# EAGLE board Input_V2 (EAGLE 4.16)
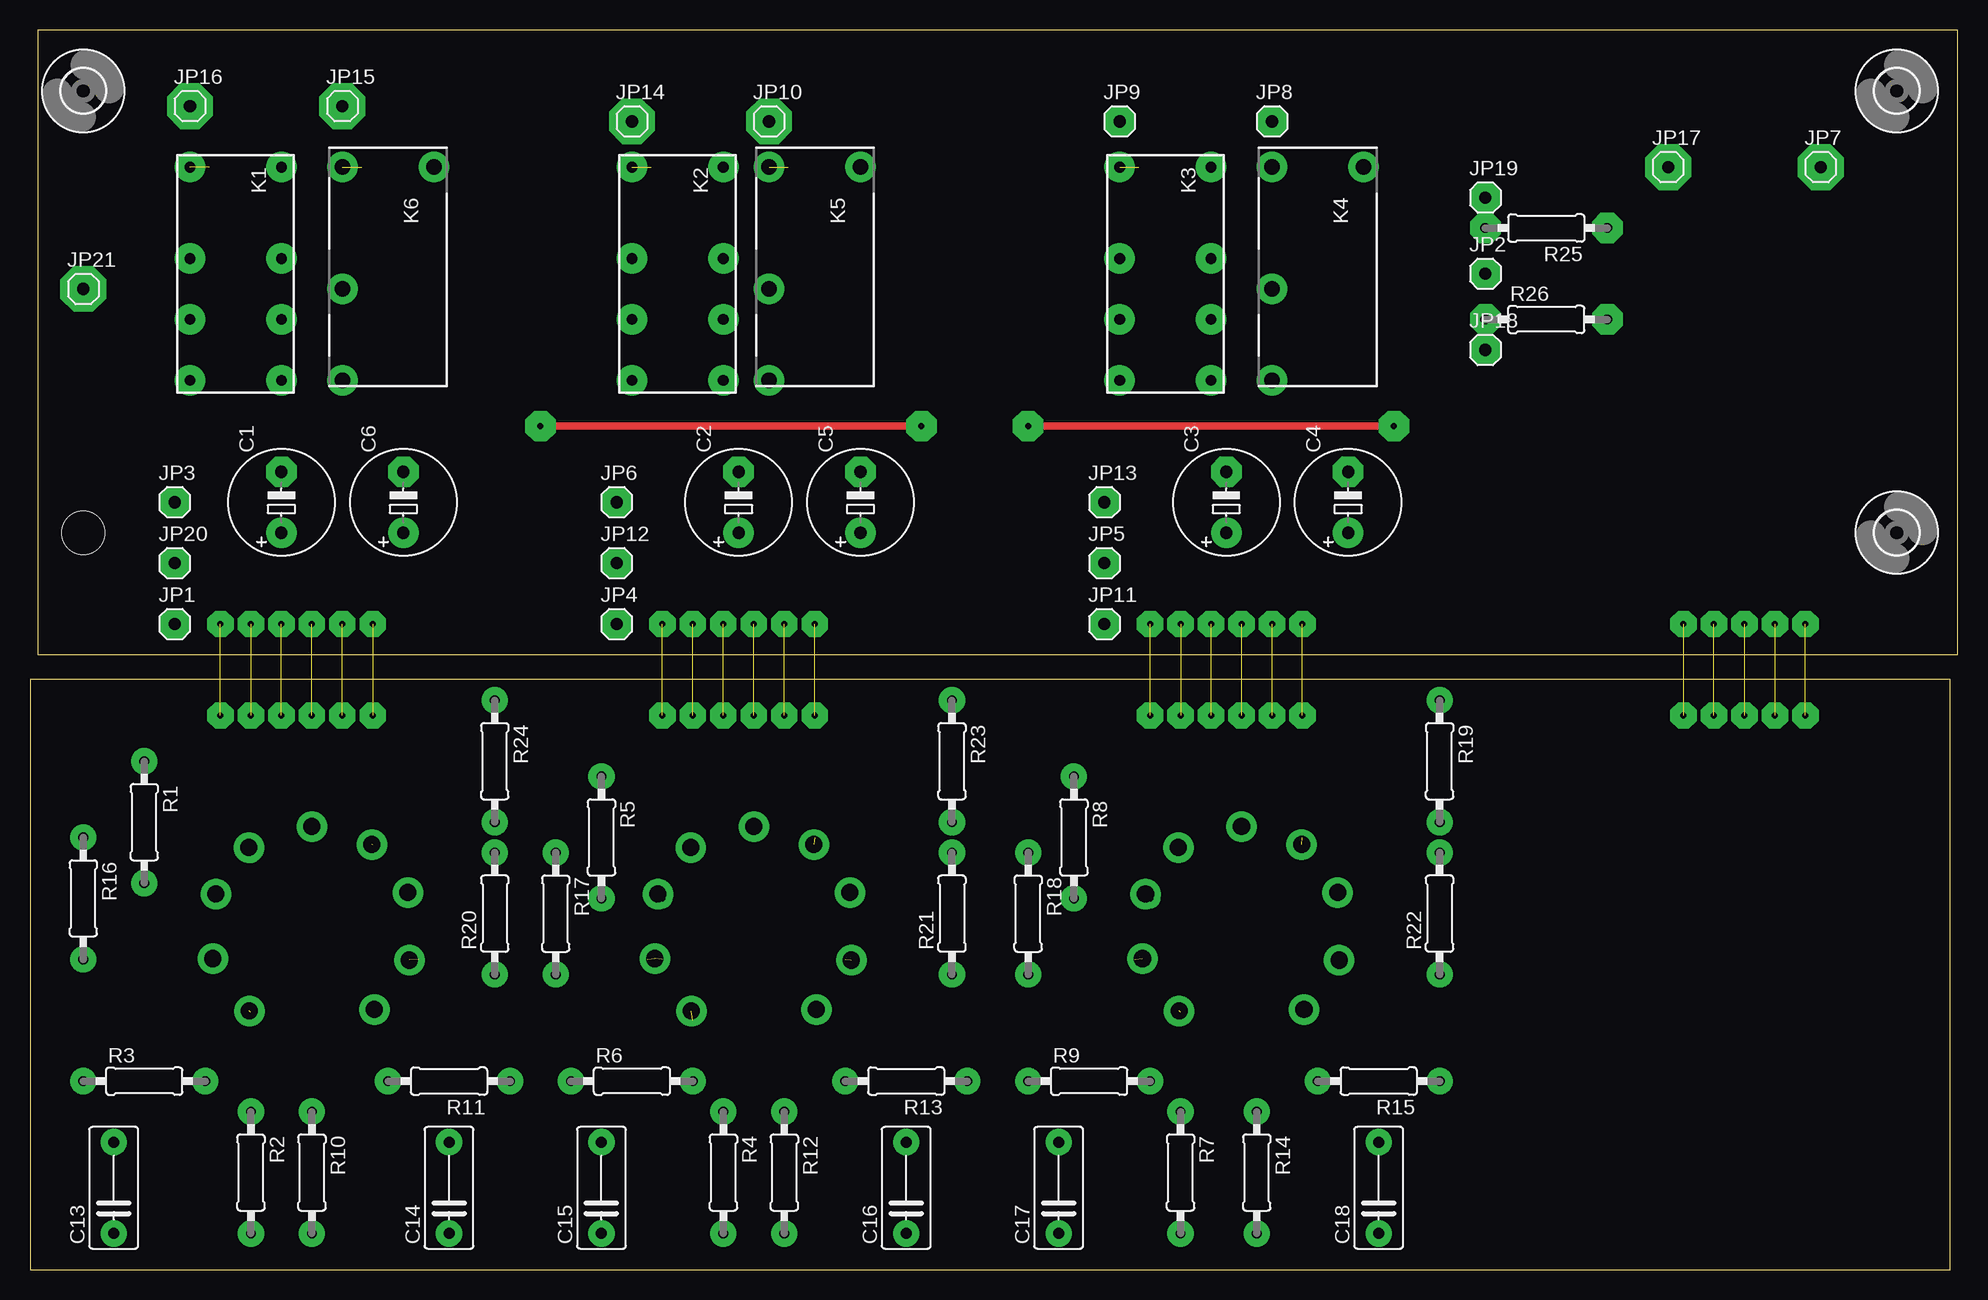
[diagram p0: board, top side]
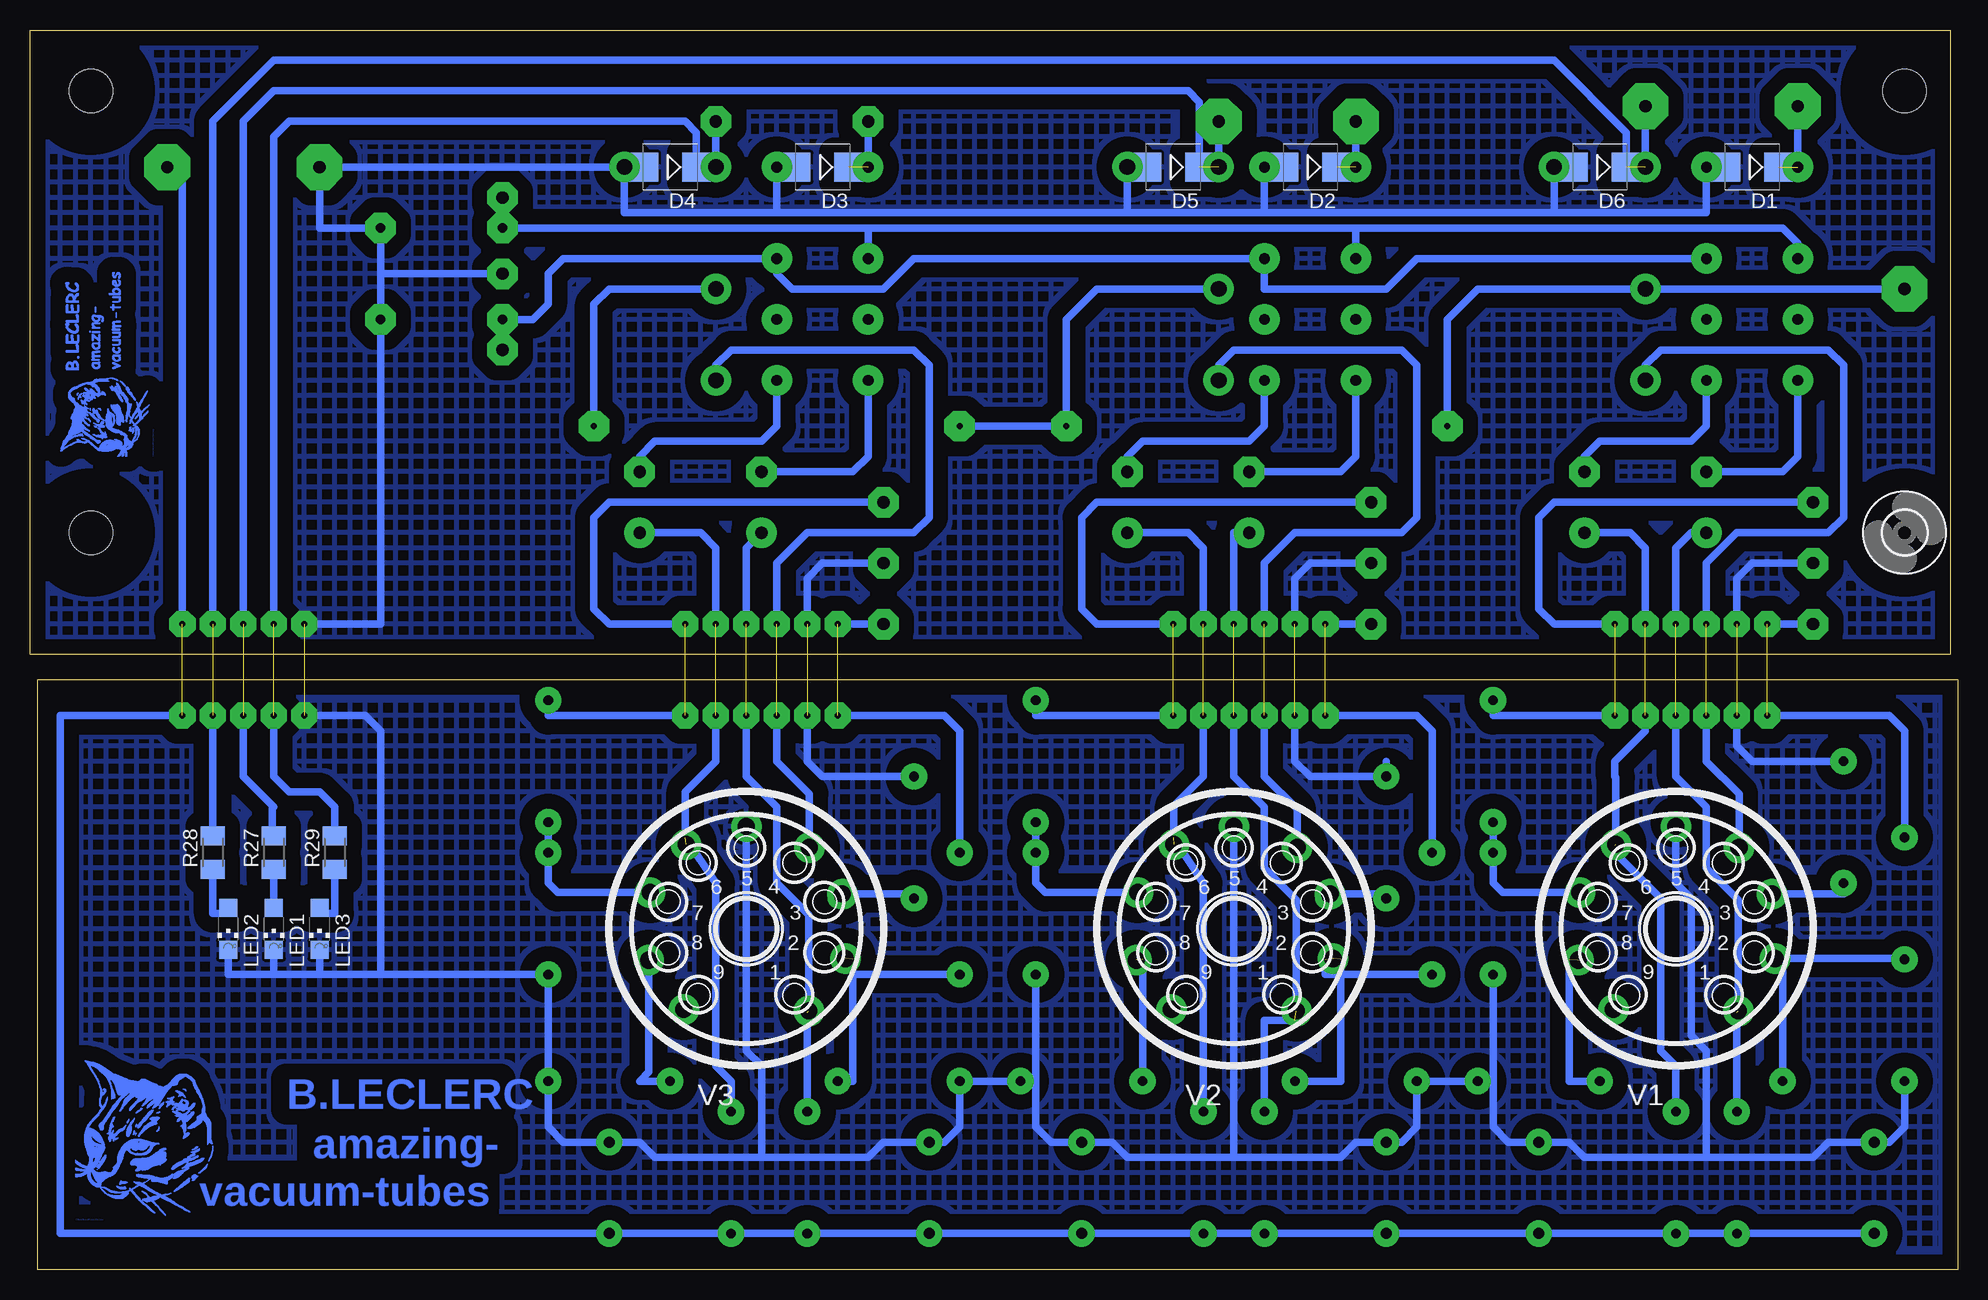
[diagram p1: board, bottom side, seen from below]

Size 160.65 x 103.34 mm. Coordinates in mm from the lower left corner, seen from the top.
Outline: 0,0 160,0 160,49.2 0,49.2 0,0
Outline: 0.63,51.27 160.65,51.27 160.65,103.34 0.63,103.34 0.63,51.27
Copper layers (1*16): Top 0.035mm / dielectric 1.5mm / Bottom 0.035mm
Design rules "default": minimum track width 10mil, minimum drill 24mil, track to track 8mil, track to pad 8mil, pad to pad 8mil, via to via 8mil, smd to smd 8mil, copper to edge 40mil, drill to drill 8mil, minimum pad ring 10mil, minimum via ring 8mil, stop-mask expansion 4mil, vias tented up to drill 0mil, thermal gap 10mil

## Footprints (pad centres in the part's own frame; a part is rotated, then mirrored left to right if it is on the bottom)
E5-8,5 = drill 1.016 pad 2.54 round: + -2.54,0 | drill 1.016 pad 2.54 octagon: - 2.54,0
C075-042X103 = drill 0.914 octagon: 1 -3.81,0; 2 3.81,0
SMB = smd 2.4 x 2.4: A 2.2,0; C -2.2,0
3,6 = hole 3.6: 0,0
1X01 = drill 1.016 octagon: 1 0,0
DS2Y = drill 0.9 round: 1 -8.89,-3.81; 4 -1.27,-3.81; 6 3.81,-3.81; 8 8.89,-3.81; 9 8.89,3.81; 11 3.81,3.81; 13 -1.27,3.81; 16 -8.89,3.81
RE-SCHRACK = drill 1.3 round: 11 8.89,-3.81; 14 1.27,-3.81; A1 -8.89,-3.81; A2 -8.89,3.81
CHIPLED_1206 = smd 1.5 x 1.5: A 0,-1.75; C 0,1.75
0207/10 = drill 0.813 octagon: 1 -5.08,0; 2 5.08,0
M1206 = smd 1.6 x 2: 1 -1.4,0; 2 1.4,0
NOVAL = drill 1.422 pad 2.54 round: 1 5.207,-6.858; 2 8.254,-2.484; 3 8.004,2.893; 4 5.258,6.77; 5 0,8.524; 6 -5.004,7.024; 7 -8.004,3.02; 8 -8.127,-2.611; 9 -5.207,-6.731

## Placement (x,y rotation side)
C1  4,7µF/100V  [E5-8,5]  20.95,63.97 90 top
C2  4,7µF/100V  [E5-8,5]  59.05,63.97 90 top
C3  4,7µF/100V  [E5-8,5]  99.69,63.97 90 top
C4  4,7µF/100V  [E5-8,5]  109.85,63.97 90 top
C5  4,7µF/100V  [E5-8,5]  69.21,63.97 90 top
C6  4,7µF/100V  [E5-8,5]  31.11,63.97 90 top
C13  0.47  [C075-042X103]  6.98,6.82 90 top
C14  0.47  [C075-042X103]  34.92,6.82 90 top
C15  0.47  [C075-042X103]  47.62,6.82 90 top
C16  0.47  [C075-042X103]  73.02,6.82 90 top
C17  0.47  [C075-042X103]  85.72,6.82 90 top
C18  0.47  [C075-042X103]  112.39,6.82 90 top
D1  1N4148  [SMB]  17.14,91.91 180 bottom
D2  1N4148  [SMB]  53.97,91.91 180 bottom
D3  1N4148  [SMB]  94.61,91.91 180 bottom
D4  1N4148  [SMB]  107.31,91.91 180 bottom
D5  1N4148  [SMB]  65.4,91.91 180 bottom
D6  1N4148  [SMB]  29.84,91.91 180 bottom
H1  MOUNT-HOLE3.6  [3,6]  4.44,61.43 0 bottom
H2  MOUNT-HOLE3.6  [3,6]  155.57,61.43 0 top
H3  MOUNT-HOLE3.6  [3,6]  155.57,98.26 0 top
H4  MOUNT-HOLE3.6  [3,6]  4.44,98.26 0 top
JP1  IN1_L  [1X01]  12.06,53.81 0 top
JP2  IN_GND_1  [1X01]  121.28,83.02 0 top
JP3  IN1_R  [1X01]  12.06,63.97 0 top
JP4  IN2_L  [1X01]  48.89,53.81 0 top
JP5  IN_GND_2  [1X01]  89.53,58.89 0 top
JP6  IN2_R  [1X01]  48.89,63.97 0 top
JP7  VCC  [1X01]  149.22,91.91 0 top
JP8  [1X01]  103.5,95.72 0 top
JP9  [1X01]  90.8,95.72 0 top
JP10  [1X01]  61.59,95.72 0 top
JP11  IN3_L  [1X01]  89.53,53.81 0 top
JP12  IN_GND_3  [1X01]  48.89,58.89 0 top
JP13  IN3_R  [1X01]  89.53,63.97 0 top
JP14  [1X01]  50.16,95.72 0 top
JP15  [1X01]  26.03,96.99 0 top
JP16  [1X01]  13.33,96.99 0 top
JP17  [1X01]  136.52,91.91 0 top
JP18  OUT_L  [1X01]  121.28,76.67 0 top
JP19  OUT_R  [1X01]  121.28,89.37 0 top
JP20  GND  [1X01]  12.06,58.89 0 top
JP21  [1X01]  4.44,81.75 0 top
K1  DS2Y-S-DC12V  [DS2Y]  17.14,83.02 270 top
K2  DS2Y-S-DC12V  [DS2Y]  53.97,83.02 270 top
K3  DS2Y-S-DC12V  [DS2Y]  94.61,83.02 270 top
K4  RE030005  [RE-SCHRACK]  107.31,83.02 270 top
K5  RE030005  [RE-SCHRACK]  65.4,83.02 270 top
K6  RE030005  [RE-SCHRACK]  29.84,83.02 270 top
LED1  Red  [CHIPLED_1206]  140.33,28.41 180 bottom
LED2  Green  [CHIPLED_1206]  144.14,28.41 180 bottom
LED3  Blue  [CHIPLED_1206]  136.52,28.41 180 bottom
R1  1K  [0207/10]  9.52,37.3 270 top
R2  10K  [0207/10]  18.41,8.09 270 top
R3  47K  [0207/10]  9.52,15.71 0 top
R4  10K  [0207/10]  57.78,8.09 270 top
R5  1K  [0207/10]  47.62,36.03 270 top
R6  47K  [0207/10]  50.16,15.71 0 top
R7  10K  [0207/10]  95.88,8.09 270 top
R8  1K  [0207/10]  86.99,36.03 270 top
R9  47K  [0207/10]  88.26,15.71 0 top
R10  10K  [0207/10]  23.49,8.09 270 top
R11  1K  [0207/10]  34.92,15.71 180 top
R12  10K  [0207/10]  62.86,8.09 270 top
R13  1K  [0207/10]  73.02,15.71 180 top
R14  10K  [0207/10]  102.23,8.09 270 top
R15  1K  [0207/10]  112.39,15.71 180 top
R16  22K  [0207/10]  4.44,30.95 270 top
R17  22K  [0207/10]  43.81,29.68 270 top
R18  22K  [0207/10]  83.18,29.68 270 top
R19  22K  [0207/10]  117.47,42.38 270 top
R20  47K  [0207/10]  38.73,29.68 90 top
R21  47K  [0207/10]  76.83,29.68 90 top
R22  47K  [0207/10]  117.47,29.68 90 top
R23  22K  [0207/10]  76.83,42.38 270 top
R24  22K  [0207/10]  38.73,42.38 270 top
R25  220K  [0207/10]  126.36,86.83 180 top
R26  220K  [0207/10]  126.36,79.21 0 top
R27  1200  [M1206]  140.33,34.76 90 bottom
R28  1200  [M1206]  145.41,34.76 90 bottom
R29  1200  [M1206]  135.25,34.76 90 bottom
U$3  [CHAT1]  156.84,4.28 0 bottom
U$4  [CHAT]  150.49,67.78 90 bottom
V1  ECC82  [NOVAL]  23.49,28.41 0 bottom
V2  ECC82  [NOVAL]  60.32,28.41 0 bottom
V3  ECC82  [NOVAL]  100.96,28.41 0 bottom

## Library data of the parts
C1-C6 C13-C18 R1-R29 = rcl
D1-D6 = diode
H1-H4 = holes
JP1-JP21 = pinhead
K1-K6 = relay
LED1-LED3 = led
U$3 U$4 = LOGO
V1-V3 = tubes

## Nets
CD-E1: D1.C JP16.1 K1.1
CD-E2: D2.C JP14.1 K2.1
CD-E3: D3.C JP9.1 K3.1
GND: C13.2 C14.2 C15.2 C16.2 C17.2 C18.2 D1.A D2.A D3.A D4.A D5.A D6.A JP2.1 JP5.1 JP12.1 JP17.1 JP20.1 K1.16 K2.16 K3.16 K4.A2 K5.A2 K6.A2 LED1.C LED2.C LED3.C R1.1 R3.1 R5.1 R6.1 R8.1 R9.1 R11.1 R13.1 R15.1 R20.1 R21.1 R22.1 R25.1 R26.2 V1.5 V3.5
N$1: C2.+ R4.1 V2.1
N$2: C3.+ R7.1 V3.1
N$3: R8.2 V3.3
N$4: C6.+ R10.1 V1.6
N$5: R11.2 V1.8
N$7: R13.2 V2.8
N$8: C4.+ R14.1 V3.6
N$9: R15.2 V3.8
N$10: R1.2 V1.3
N$11: R3.2 R16.2 V1.2
N$12: C1.+ R2.1 V1.1
N$13: JP1.1 R16.1
N$14: JP4.1 R17.1
N$15: R5.2 V2.3
N$16: JP11.1 R18.1
N$17: JP3.1 R24.1
N$18: R6.2 R17.2 V2.2
N$19: JP6.1 R23.1
N$20: R20.2 R24.2 V1.7
N$21: R9.2 R18.2 V3.2
N$22: JP13.1 R19.1
N$23: LED3.A R29.1
N$24: LED2.A R28.1
N$25: R21.2 R23.2 V2.7
N$26: LED1.A R27.1
N$27: R19.2 R22.2 V3.7
N$28: D5.C JP10.1 K5.A1 R27.2
N$30: D6.C JP15.1 K6.A1 R28.2
N$36: JP19.1 K1.4 K2.4 K3.4 R25.2
N$37: JP18.1 K1.13 K2.13 K3.13 R26.1
N$47: K4.11 V3.4
N$48: K5.11 V2.4
N$49: K6.11 V1.4
N$73: C5.+ R12.1 V2.6
N$166: D4.C JP8.1 K4.A1 R29.2
S1-L: C6.- K1.9
S1-R: C1.- K1.8
S2-L: C5.- K2.9
S2-R: C2.- K2.8
S3-L: C4.- K3.9
S3-R: C3.- K3.8
VCC: C13.1 C14.1 C15.1 C16.1 C17.1 C18.1 JP7.1 R2.2 R4.2 R7.2 R10.2 R12.2 R14.2
VCC/2: JP21.1 K4.14 K5.14 K6.14

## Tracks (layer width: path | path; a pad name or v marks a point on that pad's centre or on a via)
CD-E1  (1 unrouted)
  Bottom 0.61: K1.1 JP16.1
CD-E2  (1 unrouted)
  Bottom 0.61: K2.1 JP14.1
CD-E3  (1 unrouted)
  Bottom 0.61: K3.1 JP9.1
GND  (via drill 0.5 pad 1.68, 0.5 pad 2.18)  (4 unrouted)
  Bottom 0.61: R1.1 17.14,42.38 18.41,43.65 18.41,46.19 | JP20.1 17.14,58.89 18.41,57.62 18.41,53.81 | R3.1 4.44,11.9 5.71,10.63 C13.2 10.79,10.63 12.06,9.36 20.95,9.36 | 20.95,9.36 31.11,9.36 32.38,10.63 C14.2 37.46,10.63 38.73,11.9 38.73,15.71 | 60.32,9.36 51.43,9.36 50.16,10.63 C15.2 46.35,10.63 45.08,11.9 R6.1 R11.1 38.73,15.71 | 60.32,9.36 69.21,9.36 70.48,10.63 C16.2 75.56,10.63 76.83,11.9 76.83,15.71 | 99.69,9.36 90.8,9.36 89.53,10.63 C17.2 84.45,10.63 83.18,11.9 R9.1 R13.1 76.83,15.71 | 99.69,9.36 108.58,9.36 109.85,10.63 C18.2 116.2,10.63 117.47,11.9 R15.1 R22.1 131.44,24.6 | LED2.C 144.14,24.6 140.33,24.6 | 131.44,24.6 136.52,24.6 | 136.52,24.6 140.33,24.6 | 140.33,24.6 LED1.C | 136.52,24.6 LED3.C | 76.83,15.71 R21.1 | 38.73,15.71 R20.1 | 20.95,9.36 20.95,18.25 22.22,19.52 22.22,30.95 23.49,32.22 V1.5 23.49,37.3 | 60.32,9.36 v60.32,36.66 | v100.96,36.66 100.96,18.25 99.69,16.98 99.69,9.36 | 47.62,42.38 R5.1 53.97,41.11 55.24,42.38 55.24,46.19 | R8.1 94.61,41.11 95.88,42.38 95.88,46.19 | JP5.1 94.61,58.89 95.88,57.62 95.88,53.81 | JP12.1 53.97,58.89 55.24,57.62 55.24,53.81 | 131.44,24.6 131.44,44.92 132.71,46.19 v137.79,46.19 | 131.44,83.02 R25.1 136.52,86.83 JP17.1 K4.A2 111.12,88.1 98.42,88.1 | 131.44,83.02 JP2.1 | v137.79,53.81 131.44,53.81 R26.2 131.44,83.02 | K1.16 20.95,88.1 33.65,88.1 | 33.65,88.1 57.78,88.1 | 57.78,88.1 69.21,88.1 | 69.21,88.1 98.42,88.1 | 33.65,88.1 K6.A2 | 57.78,88.1 K2.16 | 69.21,88.1 K5.A2 | 98.42,88.1 K3.16
  pour Bottom (isolate 1.27, hatched): 0.63,48.73 159.38,48.73 159.38,0.47 0.63,0.47
  pour Bottom (isolate 1.27, hatched): 0.63,103.34 160.65,103.34 160.65,51.27 0.63,51.27 0.63,103.34 0.63,102.07
N$1  (2 unrouted)
  Bottom 0.61: R4.1 57.78,20.79 55.24,20.79 | V2.1 55.11,30.82 57.78,33.49 57.78,38.57 60.32,41.11 60.32,46.19 | C2.+ 60.32,61.43 60.32,53.81
N$2  (via drill 0.5 pad 1.68)  (2 unrouted)
  Bottom 0.61: R7.1 v95.88,21.42 95.88,22.06 | V3.1 95.75,29.55 98.42,32.22 98.42,38.57 100.96,41.11 100.96,46.19 | C3.+ 100.96,60.16 100.96,53.81
N$3
  Bottom 0.61: V3.3 87.34,31.3 R8.2
N$4  (via drill 0.5 pad 1.68)  (2 unrouted)
  Bottom 0.61: 28.57,36.03 v28.57,35.39 28.57,34.76 24.76,30.95 24.76,18.25 23.49,16.98 R10.1 | C6.+ 27.3,61.43 26.03,60.16 26.03,53.81 | V1.6 28.49,41.03 28.57,41.11 28.57,42.38 26.03,44.92 26.03,46.19
N$5  (1 unrouted)
  Bottom 0.61: R11.2 32.38,15.71 32.38,25.87
N$6  (via drill 0.5 pad 2.18)
  other vias: 140.33,46.19
N$7  (1 unrouted)
  Bottom 0.61: R13.2 67.94,25.87
N$8  (2 unrouted)
  Bottom 0.61: R14.1 102.23,15.71 103.5,16.98 103.5,32.22 106.04,36.03 106.04,39.84 103.5,42.38 103.5,46.19 | C4.+ 104.77,61.43 103.5,60.16 103.5,53.81
N$9
  Bottom 0.61: V3.8 109.09,16.47 109.85,15.71 R15.2
N$10
  Bottom 0.61: V1.3 9.52,31.3 R1.2
N$11
  Bottom 0.61: 14.6,25.93 4.44,25.93 R16.2 | 14.6,25.93 V1.2 | 14.6,25.93 R3.2
N$12  (via drill 0.5 pad 1.68)  (2 unrouted)
  Bottom 0.61: R2.1 v18.41,21.42 18.41,22.06 | C1.+ 22.22,61.43 23.49,60.16 23.49,53.81 | V1.1 18.28,30.82 20.95,33.49 20.95,38.57 23.49,41.11 23.49,46.19
N$13  (1 unrouted)
  Bottom 0.61: R16.1 4.44,44.92 5.71,46.19 15.87,46.19 | JP1.1 15.87,53.81
N$14  (1 unrouted)
  Bottom 0.61: R17.1 43.81,44.92 45.08,46.19 52.7,46.19 | JP4.1 52.7,53.81
N$15
  Bottom 0.61: V2.3 47.97,31.3 R5.2
N$16  (1 unrouted)
  Bottom 0.61: R18.1 83.18,44.92 84.45,46.19 93.34,46.19 | JP11.1 93.34,53.81
N$17  (1 unrouted)
  Bottom 0.61: R24.1 38.73,46.19 28.57,46.19 | JP3.1 33.65,63.97 34.92,62.7 34.92,55.08 33.65,53.81 28.57,53.81
N$18  (2 unrouted)
  Bottom 0.61: R17.2 52.7,24.6 52.7,25.87 | R6.2 51.43,15.71 51.43,25.87
N$19  (1 unrouted)
  Bottom 0.61: R23.1 76.83,46.19 65.4,46.19 | JP6.1 71.75,63.97 73.02,62.7 73.02,55.08 71.75,53.81 65.4,53.81
N$20
  Bottom 0.61: V1.7 37.94,31.43 38.73,32.22 R20.2 R24.2
N$21  (1 unrouted)
  Bottom 0.61: R18.2 92.07,24.6 92.07,25.87 92.07,15.71 R9.2
N$22  (1 unrouted)
  Bottom 0.61: R19.1 117.47,46.19 106.04,46.19 | JP13.1 112.39,63.97 113.66,62.7 113.66,55.08 112.39,53.81 106.04,53.81
N$23
  Bottom 0.61: R29.1 135.25,29.68 136.52,29.68 LED3.A
N$24
  Bottom 0.61: R28.1 145.41,29.68 144.14,29.68 LED2.A
N$25
  Bottom 0.61: V2.7 76.04,31.43 76.83,32.22 R21.2 R23.2
N$26
  Bottom 0.61: 140.33,29.68 LED1.A R27.1
N$27
  Bottom 0.61: V3.7 116.68,31.43 117.47,32.22 R22.2 R19.2
N$28  (2 unrouted)
  Bottom 0.61: R27.2 140.46,36.16 140.46,38.44 140.33,38.57 142.87,41.11 142.87,46.19 | K5.A1 JP10.1 | 142.87,53.81 142.87,95.72 140.33,98.26 64.13,98.26 63.2,97.33 D5.C
N$29  (via drill 0.5 pad 3.81)
  other vias: 4.44,81.75
N$30  (2 unrouted)
  Bottom 0.61: R28.2 145.41,46.19 | 27.64,93.52 D6.C 27.64,94.79 33.65,100.8 140.33,100.8 145.41,95.72 145.41,53.81 | K6.A1 JP15.1
N$31  (via drill 0.5 pad 2.18)
  other vias: 140.33,53.81
N$32  (via drill 0.5 pad 2.18)
  other vias: 142.87,46.19
N$33  (via drill 0.5 pad 2.18)
  other vias: 142.87,53.81
N$34  (via drill 0.5 pad 2.54)
  other vias: 42.54,70.32
N$35  (via drill 0.5 pad 2.54)
  other vias: 74.29,70.32
N$36
  Bottom 0.61: K1.4 13.33,85.56 14.6,86.83 50.16,86.83 | 50.16,86.83 90.8,86.83 | 90.8,86.83 R25.2 JP19.1 | 50.16,86.83 K2.4 | 90.8,86.83 K3.4
N$37
  Bottom 0.61: K1.13 45.08,84.29 47.62,81.75 57.78,81.75 K2.13 86.99,84.29 89.53,81.75 97.15,81.75 98.42,83.02 K3.13 116.2,84.29 117.47,83.02 117.47,80.48 118.74,79.21 R26.1 JP18.1
N$38  (via drill 0.5 pad 2.18)
  other vias: 100.96,46.19
N$39  (via drill 0.5 pad 2.18)
  other vias: 103.5,46.19
N$40  (via drill 0.5 pad 2.18)
  other vias: 98.42,46.19
N$41  (via drill 0.5 pad 2.18)
  other vias: 98.42,53.81
N$42  (via drill 0.5 pad 2.18)
  other vias: 100.96,53.81
N$43  (via drill 0.5 pad 2.18)
  other vias: 103.5,53.81
N$44  (via drill 0.5 pad 2.18)
  other vias: 60.32,46.19
N$45  (via drill 0.5 pad 2.18)
  other vias: 62.86,46.19
N$46  (via drill 0.5 pad 2.18)
  other vias: 57.78,46.19
N$47  (1 unrouted)
  Bottom 0.61: V3.4 95.7,39.66 98.42,42.38 98.42,46.19 | K4.11 103.5,75.4 102.23,76.67 86.99,76.67 85.72,75.4 85.72,62.7 86.99,61.43 95.88,61.43 98.42,58.89 98.42,53.81
N$48  (1 unrouted)
  Bottom 0.61: V2.4 55.06,38.39 57.78,41.11 57.78,46.19 | K5.11 61.59,75.4 60.32,76.67 46.35,76.67 45.08,75.4 45.08,62.7 46.35,61.43 55.24,61.43 57.78,58.89 57.78,53.81
N$49  (1 unrouted)
  Bottom 0.61: V1.4 18.23,39.66 20.95,42.38 20.95,46.19 | K6.11 26.03,75.4 24.76,76.67 10.79,76.67 9.52,75.4 9.52,62.7 10.79,61.43 18.41,61.43 20.95,58.89 20.95,53.81
N$50  (via drill 0.5 pad 2.18)
  other vias: 23.49,46.19
N$51  (via drill 0.5 pad 2.18)
  other vias: 26.03,46.19
N$52  (via drill 0.5 pad 2.18)
  other vias: 20.95,46.19
N$53  (via drill 0.5 pad 2.18)
  other vias: 20.95,53.81
N$54  (via drill 0.5 pad 2.18)
  other vias: 23.49,53.81
N$55  (via drill 0.5 pad 2.18)
  other vias: 26.03,53.81
N$56  (via drill 0.5 pad 2.18)
  other vias: 57.78,53.81
N$57  (via drill 0.5 pad 2.18)
  other vias: 60.32,53.81
N$58  (via drill 0.5 pad 2.18)
  other vias: 62.86,53.81
N$59  (via drill 0.5 pad 2.18)
  other vias: 28.57,46.19
N$60  (via drill 0.5 pad 2.18)
  other vias: 28.57,53.81
N$61  (via drill 0.5 pad 2.18)
  other vias: 18.41,46.19
N$62  (via drill 0.5 pad 2.18)
  other vias: 18.41,53.81
N$63  (via drill 0.5 pad 2.18)
  other vias: 15.87,46.19
N$64  (via drill 0.5 pad 2.18)
  other vias: 15.87,53.81
N$65  (via drill 0.5 pad 2.18)
  other vias: 65.4,46.19
N$66  (via drill 0.5 pad 2.18)
  other vias: 65.4,53.81
N$67  (via drill 0.5 pad 2.18)
  other vias: 55.24,46.19
N$68  (via drill 0.5 pad 2.18)
  other vias: 55.24,53.81
N$69  (via drill 0.5 pad 2.18)
  other vias: 52.7,46.19
N$70  (via drill 0.5 pad 2.18)
  other vias: 52.7,53.81
N$71  (via drill 0.5 pad 2.18)
  other vias: 106.04,46.19
N$72  (via drill 0.5 pad 2.18)
  other vias: 106.04,53.81
N$73  (2 unrouted)
  Bottom 0.61: R12.1 62.86,32.22 65.4,36.03 | V2.6 65.32,38.65 62.86,41.11 62.86,46.19 | C5.+ 64.13,61.43 62.86,60.16 62.86,53.81
N$74  (via drill 0.5 pad 2.18)
  other vias: 95.88,46.19
N$75  (via drill 0.5 pad 2.18)
  other vias: 95.88,53.81
N$76  (via drill 0.5 pad 2.18)
  other vias: 93.34,46.19
N$77  (via drill 0.5 pad 2.18)
  other vias: 93.34,53.81
N$78  (via drill 0.5 pad 2.18)
  other vias: 145.41,46.19
N$79  (via drill 0.5 pad 2.18)
  other vias: 145.41,53.81
N$80  (via drill 0.5 pad 2.18)
  other vias: 147.95,46.19
N$81  (via drill 0.5 pad 2.18)
  other vias: 147.95,53.81
N$82  (via drill 0.5 pad 2.18)
  other vias: 40,15.71
N$83  (via drill 0.5 pad 2.18)
  other vias: 38.73,24.6
N$84  (via drill 0.5 pad 2.18)
  other vias: 38.73,34.76
N$85  (via drill 0.5 pad 2.18)
  other vias: 38.73,37.3
N$86  (via drill 0.5 pad 2.18)
  other vias: 38.73,47.46
N$87  (via drill 0.5 pad 2.18)
  other vias: 57.78,3.01
N$88  (via drill 0.5 pad 2.18)
  other vias: 57.78,13.17
N$89  (via drill 0.5 pad 2.18)
  other vias: 47.62,3.01
N$90  (via drill 0.5 pad 2.18)
  other vias: 47.62,10.63
N$91  (via drill 0.5 pad 2.18)
  other vias: 55.24,15.71
N$92  (via drill 0.5 pad 2.18)
  other vias: 45.08,15.71
N$93  (via drill 0.5 pad 2.18)
  other vias: 43.81,24.6
N$94  (via drill 0.5 pad 2.18)
  other vias: 43.81,34.76
N$95  (via drill 0.5 pad 2.18)
  other vias: 47.62,30.95
N$96  (via drill 0.5 pad 2.18)
  other vias: 47.62,41.11
N$97  (via drill 0.5 pad 2.18)
  other vias: 62.86,3.01
N$98  (via drill 0.5 pad 2.18)
  other vias: 62.86,13.17
N$99  (via drill 0.5 pad 2.18)
  other vias: 73.02,3.01
N$100  (via drill 0.5 pad 2.18)
  other vias: 73.02,10.63
N$101  (via drill 0.5 pad 2.18)
  other vias: 67.94,15.71
N$102  (via drill 0.5 pad 2.18)
  other vias: 78.1,15.71
N$103  (via drill 0.5 pad 2.18)
  other vias: 76.83,24.6
N$104  (via drill 0.5 pad 2.18)
  other vias: 76.83,34.76
N$105  (via drill 0.5 pad 2.18)
  other vias: 76.83,37.3
N$106  (via drill 0.5 pad 2.18)
  other vias: 76.83,47.46
N$107  (via drill 0.5 pad 2.18)
  other vias: 86.99,41.11
N$108  (via drill 0.5 pad 2.18)
  other vias: 83.18,34.76
N$109  (via drill 0.5 pad 2.18)
  other vias: 86.99,30.95
N$110  (via drill 0.5 pad 2.18)
  other vias: 83.18,24.6
N$111  (via drill 0.5 pad 2.18)
  other vias: 83.18,15.71
N$112  (via drill 0.5 pad 2.18)
  other vias: 93.34,15.71
N$113  (via drill 0.5 pad 2.18)
  other vias: 85.72,10.63
N$114  (via drill 0.5 pad 2.18)
  other vias: 85.72,3.01
N$115  (via drill 0.5 pad 2.18)
  other vias: 95.88,13.17
N$116  (via drill 0.5 pad 2.18)
  other vias: 95.88,3.01
N$117  (via drill 0.5 pad 2.18)
  other vias: 117.47,47.46
N$118  (via drill 0.5 pad 2.18)
  other vias: 117.47,37.3
N$119  (via drill 0.5 pad 2.18)
  other vias: 117.47,34.76
N$120  (via drill 0.5 pad 2.18)
  other vias: 117.47,24.6
N$121  (via drill 0.5 pad 2.18)
  other vias: 102.23,3.01
N$122  (via drill 0.5 pad 2.18)
  other vias: 102.23,13.17
N$123  (via drill 0.5 pad 2.18)
  other vias: 107.31,15.71
N$124  (via drill 0.5 pad 2.18)
  other vias: 117.47,15.71
N$125  (via drill 0.5 pad 2.18)
  other vias: 112.39,10.63
N$126  (via drill 0.5 pad 2.18)
  other vias: 112.39,3.01
N$127  (via drill 0.5 pad 2.18)
  other vias: 29.84,15.71
N$128  (via drill 0.5 pad 2.18)
  other vias: 34.92,3.01
N$129  (via drill 0.5 pad 2.18)
  other vias: 34.92,10.63
N$130  (via drill 0.5 pad 2.18)
  other vias: 4.44,25.87
N$131  (via drill 0.5 pad 2.18)
  other vias: 4.44,36.03
N$132  (via drill 0.5 pad 2.18)
  other vias: 9.52,32.22
N$133  (via drill 0.5 pad 2.18)
  other vias: 9.52,42.38
N$134  (via drill 0.5 pad 2.18)
  other vias: 18.41,3.01
N$135  (via drill 0.5 pad 2.18)
  other vias: 18.41,13.17
N$136  (via drill 0.5 pad 2.18)
  other vias: 23.49,3.01
N$137  (via drill 0.5 pad 2.18)
  other vias: 23.49,13.17
N$138  (via drill 0.5 pad 2.18)
  other vias: 4.44,15.71
N$139  (via drill 0.5 pad 2.18)
  other vias: 14.6,15.71
N$140  (via drill 0.5 pad 2.18)
  other vias: 6.98,3.01
N$141  (via drill 0.5 pad 2.18)
  other vias: 6.98,10.63
N$142  (via drill 0.5 pad 1.68)
  other vias: 15.87,31.58
N$143  (via drill 0.5 pad 1.68)
  other vias: 18.41,34.76
N$144  (via drill 0.5 pad 1.68)
  other vias: 23.49,37.3
N$145  (via drill 0.5 pad 1.68)
  other vias: 31.74,31.58
N$146  (via drill 0.5 pad 1.68)
  other vias: 31.74,25.87
N$147  (via drill 0.5 pad 1.68)
  other vias: 28.57,21.42
N$148  (via drill 0.5 pad 1.68)
  other vias: 15.24,25.87
N$149  (via drill 0.5 pad 1.68)
  other vias: 55.24,21.42
N$150  (via drill 0.5 pad 1.68)
  other vias: 52.07,25.87
N$151  (via drill 0.5 pad 1.68)
  other vias: 52.7,30.95
N$152  (via drill 0.5 pad 1.68)
  other vias: 55.24,35.39
N$153  (via drill 0.5 pad 1.68)
  other vias: 65.4,35.39
N$154  (via drill 0.5 pad 1.68)
  other vias: 68.57,31.58
N$155  (via drill 0.5 pad 1.68)
  other vias: 68.57,25.87
N$156  (via drill 0.5 pad 1.68)
  other vias: 65.4,21.42
N$157  (via drill 0.5 pad 1.68)
  other vias: 92.7,25.87
N$158  (via drill 0.5 pad 1.68)
  other vias: 93.34,30.95
N$159  (via drill 0.5 pad 1.68)
  other vias: 95.88,35.39
N$160  (via drill 0.5 pad 1.68)
  other vias: 106.04,35.39
N$161  (via drill 0.5 pad 1.68)
  other vias: 109.21,31.58
N$162  (via drill 0.5 pad 1.68)
  other vias: 109.21,25.87
N$163  (via drill 0.5 pad 1.68)
  other vias: 106.04,21.42
N$164  (via drill 0.5 pad 2.54)
  other vias: 83.18,70.32
N$165  (via drill 0.5 pad 2.54)
  other vias: 113.66,70.32
N$166  (1 unrouted)
  Bottom 0.61: R29.2 135.25,38.57 136.52,39.84 139.06,39.84 140.33,41.11 140.33,46.19 | JP8.1 K4.A1 D4.C 105.11,94.79 106.04,95.72 139.06,95.72 140.33,94.45 140.33,53.81
N$167  (via drill 0.5 pad 3.81)
  other vias: 13.33,96.99
N$168  (via drill 0.5 pad 3.81)
  other vias: 26.03,96.99
N$169  (via drill 0.5 pad 3.81)
  other vias: 50.16,95.72
N$170  (via drill 0.5 pad 3.81)
  other vias: 61.59,95.72
N$171  (via drill 0.5 pad 2.54)
  other vias: 12.06,53.81
N$172  (via drill 0.5 pad 2.54)
  other vias: 12.06,58.89
N$173  (via drill 0.5 pad 3.81)
  other vias: 136.52,91.91
N$174  (via drill 0.5 pad 3.81)
  other vias: 149.22,91.91
N$175  (via drill 0.5 pad 2.54)
  other vias: 12.06,63.97
N$176  (via drill 0.5 pad 2.54)
  other vias: 48.89,53.81
N$177  (via drill 0.5 pad 2.54)
  other vias: 48.89,58.89
N$178  (via drill 0.5 pad 2.54)
  other vias: 48.89,63.97
N$179  (via drill 0.5 pad 2.54)
  other vias: 89.53,53.81
N$180  (via drill 0.5 pad 2.54)
  other vias: 89.53,58.89
N$181  (via drill 0.5 pad 2.54)
  other vias: 89.53,63.97
N$182  (via drill 0.5 pad 2.54)
  other vias: 121.28,83.02
N$183  (via drill 0.5 pad 2.54)
  other vias: 121.28,89.37
N$184  (via drill 0.5 pad 2.54)
  other vias: 121.28,76.67
N$185  (via drill 0.5 pad 2.54)
  other vias: 90.8,95.72
N$186  (via drill 0.5 pad 2.54)
  other vias: 103.5,95.72
N$187  (via drill 0.5 pad 2.54)
  other vias: 121.28,86.83
N$188  (via drill 0.5 pad 2.54)
  other vias: 131.44,86.83
N$189  (via drill 0.5 pad 2.54)
  other vias: 121.28,79.21
N$190  (via drill 0.5 pad 2.54)
  other vias: 131.44,79.21
N$191  (via drill 0.5 pad 2.54)
  other vias: 20.95,91.91
N$192  (via drill 0.5 pad 2.54)
  other vias: 20.95,84.29
N$193  (via drill 0.5 pad 2.54)
  other vias: 13.33,91.91
N$194  (via drill 0.5 pad 2.54)
  other vias: 13.33,84.29
N$195  (via drill 0.5 pad 2.54)
  other vias: 20.95,79.21
N$196  (via drill 0.5 pad 2.54)
  other vias: 20.95,74.13
N$197  (via drill 0.5 pad 2.54)
  other vias: 13.33,79.21
N$198  (via drill 0.5 pad 2.54)
  other vias: 13.33,74.13
N$199  (via drill 0.5 pad 2.54)
  other vias: 50.16,91.91
N$200  (via drill 0.5 pad 2.54)
  other vias: 57.78,91.91
N$201  (via drill 0.5 pad 2.54)
  other vias: 57.78,84.29
N$202  (via drill 0.5 pad 2.54)
  other vias: 50.16,84.29
N$203  (via drill 0.5 pad 2.54)
  other vias: 50.16,79.21
N$204  (via drill 0.5 pad 2.54)
  other vias: 57.78,79.21
N$205  (via drill 0.5 pad 2.54)
  other vias: 57.78,74.13
N$206  (via drill 0.5 pad 2.54)
  other vias: 50.16,74.13
N$207  (via drill 0.5 pad 2.54)
  other vias: 98.42,84.29
N$208  (via drill 0.5 pad 2.54)
  other vias: 98.42,91.91
N$209  (via drill 0.5 pad 2.54)
  other vias: 98.42,79.21
N$210  (via drill 0.5 pad 2.54)
  other vias: 90.8,79.21
N$211  (via drill 0.5 pad 2.54)
  other vias: 90.8,84.29
N$212  (via drill 0.5 pad 2.54)
  other vias: 90.8,91.91
N$213  (via drill 0.5 pad 2.54)
  other vias: 90.8,74.13
N$214  (via drill 0.5 pad 2.54)
  other vias: 98.42,74.13
N$215  (via drill 0.5 pad 2.54)
  other vias: 33.65,91.91
N$216  (via drill 0.5 pad 2.54)
  other vias: 26.03,81.75
N$217  (via drill 0.5 pad 2.54)
  other vias: 26.03,91.91
N$218  (via drill 0.5 pad 2.54)
  other vias: 26.03,74.13
N$219  (via drill 0.5 pad 2.54)
  other vias: 61.59,81.75
N$220  (via drill 0.5 pad 2.54)
  other vias: 61.59,74.13
N$221  (via drill 0.5 pad 2.54)
  other vias: 69.21,91.91
N$222  (via drill 0.5 pad 2.54)
  other vias: 61.59,91.91
N$223  (via drill 0.5 pad 2.54)
  other vias: 103.5,91.91
N$224  (via drill 0.5 pad 2.54)
  other vias: 103.5,81.75
N$225  (via drill 0.5 pad 2.54)
  other vias: 111.12,91.91
N$226  (via drill 0.5 pad 2.54)
  other vias: 103.5,74.13
N$227  (via drill 0.5 pad 1.27)
  other vias: 20.95,66.51
N$228  (via drill 0.5 pad 1.27)
  other vias: 31.11,66.51
N$229  (via drill 0.5 pad 1.27)
  other vias: 20.95,61.43
N$230  (via drill 0.5 pad 1.27)
  other vias: 31.11,61.43
N$231  (via drill 0.5 pad 1.27)
  other vias: 59.05,66.51
N$232  (via drill 0.5 pad 1.27)
  other vias: 59.05,61.43
N$233  (via drill 0.5 pad 1.27)
  other vias: 69.21,61.43
N$234  (via drill 0.5 pad 1.27)
  other vias: 69.21,66.51
N$235  (via drill 0.5 pad 1.27)
  other vias: 99.69,66.51
N$236  (via drill 0.5 pad 1.27)
  other vias: 99.69,61.43
N$237  (via drill 0.5 pad 1.27)
  other vias: 109.85,61.43
N$238  (via drill 0.5 pad 1.27)
  other vias: 109.85,66.51
S1-L
  Bottom 0.61: K1.9 20.95,70.32 22.22,69.05 29.84,69.05 31.11,67.78 C6.-
S1-R
  Bottom 0.61: K1.8 13.33,67.78 14.6,66.51 C1.-
S2-L
  Bottom 0.61: K2.9 57.78,70.32 59.05,69.05 67.94,69.05 69.21,67.78 C5.-
S2-R
  Bottom 0.61: K2.8 50.16,67.78 51.43,66.51 C2.-
S3-L
  Bottom 0.61: K3.9 98.42,70.32 99.69,69.05 108.58,69.05 109.85,67.78 C4.-
S3-R
  Bottom 0.61: K3.8 90.8,67.78 92.07,66.51 C3.-
VCC  (1 unrouted)
  Bottom 0.61: C13.1 R2.2 R10.2 C14.1 C15.1 R4.2 R12.2 C16.1 C17.1 R7.2 R14.2 C18.1 158.11,3.01 158.11,46.19 147.95,46.19 | JP7.1 147.95,90.64 147.95,53.81
VCC/2  (via drill 0.5 pad 2.54)  (2 unrouted)
  Top 0.61: v42.54,70.32 74.29,70.32 | v83.18,70.32 113.66,70.32
  Bottom 0.61: JP21.1 K6.14 40,81.75 42.54,79.21 v42.54,70.32 | K5.14 71.75,81.75 74.29,79.21 74.29,70.32 v83.18,70.32 | K4.14 112.39,81.75 113.66,80.48 113.66,70.32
